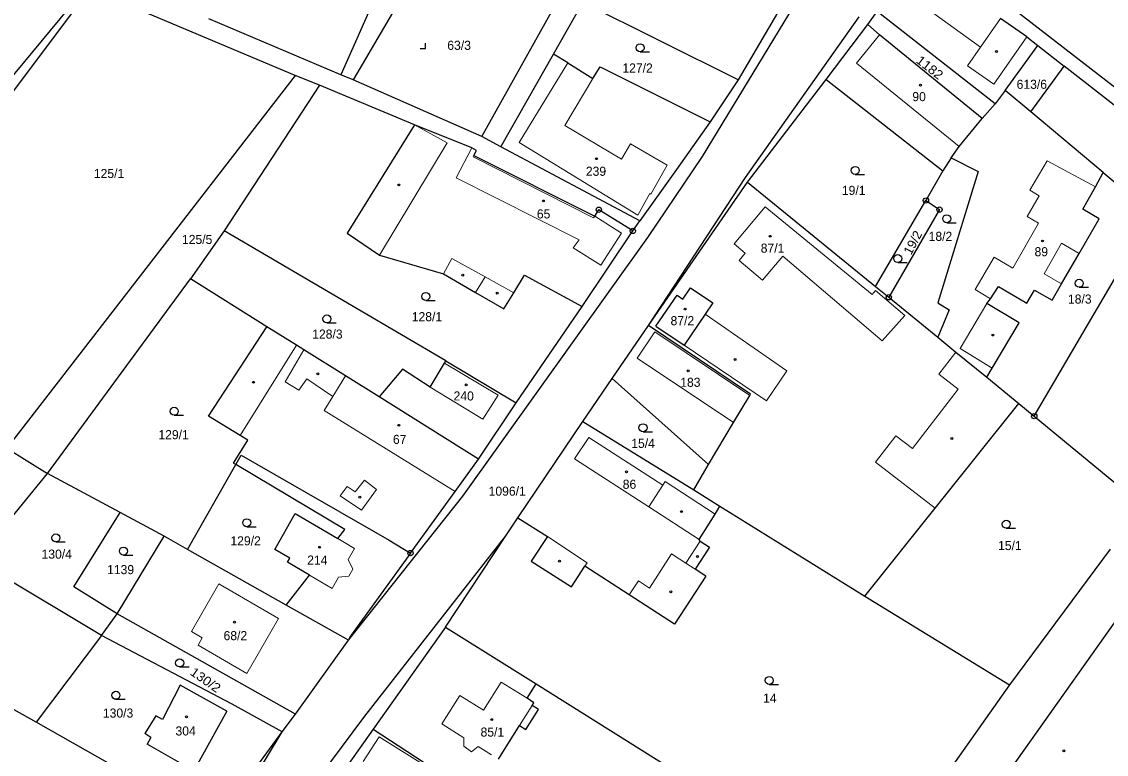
# Model space of a CAD drawing. Extents: x -694609 to -690140, y -1033292 to -1029794.
# Drawn here: x -692506.4 to -692303.2, y -1031705.3 to -1031568.1 of the extents above; entities that cross this region are included whole.
import ezdxf
from ezdxf.enums import TextEntityAlignment as Align

# ---------------------------------------------------------------- set-up
doc = ezdxf.new("R2010")
doc.units = 0
doc.header["$LTSCALE"] = 0.68
for name, color, linetype, lineweight in [('1', 7, 'Continuous', 25), ('3', 7, 'Continuous', 25), ('4', 7, 'Continuous', 13), ('5', 7, 'Continuous', 25), ('8', 7, 'Continuous', 25)]:
    doc.layers.add(name, color=color, linetype=linetype, lineweight=lineweight)
doc.layers.add('2', color=7, linetype='Continuous')

msp = doc.modelspace()

# ---------------------------------------------------------------- linework, layer by layer
at = {"layer": '1'}
for p, q in [((-692378.81, -1031593.37), (-692351.95, -1031549.08)), ((-692428.58, -1031552.29), (-692444.25, -1031578.99)), ((-692435.86, -1031553.94), (-692446.6, -1031578.05)), ((-692273.27, -1031602.4), (-692330.34, -1031558.16)), ((-692546.37, -1031624.62), (-692494.27, -1031561.65)), ((-692542.42, -1031627.11), (-692493.57, -1031562)), ((-692455.1, -1031578.2), (-692493.57, -1031562)), ((-692420.15, -1031589.65), (-692405.41, -1031563.18)), ((-692406.71, -1031574.21), (-692401.26, -1031564.53)), ((-692324.02, -1031583.53), (-692346.14, -1031566.21)), ((-692446.6, -1031578.05), (-692471.27, -1031567.56)), ((-692370.79, -1031597.28), (-692349.51, -1031567.24)), ((-692318.1, -1031570.94), (-692323.02, -1031567.51)), ((-692355.65, -1031578.92), (-692347.88, -1031568.63)), ((-692326.43, -1031586.25), (-692345.68, -1031570.59)), ((-692322.14, -1031581), (-692316.04, -1031572.55)), ((-692318.1, -1031570.94), (-692316.04, -1031572.55)), ((-692316.04, -1031572.55), (-692311.08, -1031576.44)), ((-692416.63, -1031591.56), (-692406.71, -1031574.21)), ((-692404.06, -1031575.84), (-692406.71, -1031574.21)), ((-692404.06, -1031575.84), (-692399.35, -1031578.78)), ((-692399.35, -1031578.78), (-692397.97, -1031576.56)), ((-692397.97, -1031576.56), (-692377.39, -1031586.86)), ((-692317.35, -1031585.02), (-692311.08, -1031576.44)), ((-692278.15, -1031602.2), (-692311.08, -1031576.44)), ((-692455.1, -1031578.2), (-692509.11, -1031648.01)), ((-692450.6, -1031579.99), (-692455.1, -1031578.2)), ((-692444.25, -1031578.99), (-692446.6, -1031578.05)), ((-692450.6, -1031579.99), (-692468.43, -1031607.31)), ((-692432.76, -1031587.45), (-692450.6, -1031579.99)), ((-692420.15, -1031589.65), (-692444.25, -1031578.99)), ((-692372.16, -1031579.03), (-692377.39, -1031586.86)), ((-692370.39, -1031598.15), (-692355.65, -1031578.92)), ((-692355.65, -1031578.92), (-692333.82, -1031596.07)), ((-692322.14, -1031581), (-692324.02, -1031583.53)), ((-692317.35, -1031585.02), (-692322.14, -1031581)), ((-692326.43, -1031586.25), (-692324.02, -1031583.53)), ((-692377.39, -1031586.86), (-692383.68, -1031595.82)), ((-692330.76, -1031591.49), (-692326.43, -1031586.25)), ((-692303.76, -1031596.37), (-692317.35, -1031585.02)), ((-692432.76, -1031587.45), (-692445.38, -1031607.72)), ((-692422.03, -1031591.76), (-692432.76, -1031587.45)), ((-692416.63, -1031591.56), (-692420.15, -1031589.65)), ((-692421.15, -1031592.23), (-692422.03, -1031591.76)), ((-692421.63, -1031593.17), (-692421.15, -1031592.23)), ((-692390.58, -1031605.45), (-692416.63, -1031591.56)), ((-692332.22, -1031593.61), (-692330.76, -1031591.49)), ((-692421.63, -1031593.17), (-692399.01, -1031604.57)), ((-692389.09, -1031608.56), (-692378.81, -1031593.37)), ((-692332.22, -1031593.61), (-692333.82, -1031596.07)), ((-692332.22, -1031593.61), (-692327.2, -1031596.19)), ((-692383.68, -1031595.82), (-692390.58, -1031605.45)), ((-692333.82, -1031596.07), (-692336.98, -1031601.61)), ((-692327.2, -1031596.19), (-692334.77, -1031620.8)), ((-692303.76, -1031596.37), (-692294.5, -1031604.11)), ((-692388.92, -1031625), (-692370.79, -1031597.28)), ((-692388.92, -1031625), (-692370.39, -1031598.15)), ((-692370.39, -1031598.15), (-692346.41, -1031617.72)), ((-692346.41, -1031617.72), (-692336.98, -1031601.61)), ((-692336.98, -1031601.61), (-692334.43, -1031603.32)), ((-692399.01, -1031604.57), (-692398.24, -1031603.34)), ((-692391.88, -1031607.32), (-692398.24, -1031603.34)), ((-692334.43, -1031603.32), (-692343.93, -1031619.74)), ((-692308.26, -1031611.52), (-692304.51, -1031605.04)), ((-692304.51, -1031605.04), (-692307.58, -1031603.22)), ((-692391.88, -1031607.32), (-692390.58, -1031605.45)), ((-692445.38, -1031607.72), (-692439.36, -1031611.84)), ((-692423.7, -1031656.97), (-692389.09, -1031608.56)), ((-692401.36, -1031621.44), (-692391.88, -1031607.32)), ((-692439.36, -1031611.84), (-692427.37, -1031615.38)), ((-692311.57, -1031617.22), (-692308.26, -1031611.52)), ((-692501.49, -1031652.74), (-692474.72, -1031616.29)), ((-692460.42, -1031625.25), (-692474.72, -1031616.29)), ((-692427.37, -1031615.38), (-692421.34, -1031618.84)), ((-692414.18, -1031618.89), (-692412.16, -1031615.61)), ((-692412.16, -1031615.61), (-692401.36, -1031621.44)), ((-692316.68, -1031642.01), (-692301.64, -1031616.32)), ((-692313.32, -1031620.27), (-692311.57, -1031617.22)), ((-692421.34, -1031618.84), (-692416.02, -1031621.89)), ((-692416.02, -1031621.89), (-692414.18, -1031618.89)), ((-692387.58, -1031625.14), (-692383.57, -1031619.37)), ((-692383.57, -1031619.37), (-692382.53, -1031620.1)), ((-692382.53, -1031620.1), (-692381.09, -1031617.95)), ((-692381.09, -1031617.95), (-692376.9, -1031620.81)), ((-692346.41, -1031617.72), (-692343.93, -1031619.74)), ((-692318.09, -1031620.86), (-692316.64, -1031618.4)), ((-692316.64, -1031618.4), (-692313.32, -1031620.27)), ((-692376.9, -1031620.81), (-692378.36, -1031622.93)), ((-692343.93, -1031619.74), (-692334.74, -1031627.24)), ((-692334.77, -1031620.8), (-692332.64, -1031622.09)), ((-692325.54, -1031620.92), (-692324.89, -1031620.04)), ((-692319.54, -1031624.55), (-692325.54, -1031620.92)), ((-692413.75, -1031639.49), (-692401.36, -1031621.44)), ((-692378.36, -1031622.93), (-692382.25, -1031628.74)), ((-692332.64, -1031622.09), (-692334.74, -1031627.24)), ((-692471.34, -1031642.04), (-692460.42, -1031625.25)), ((-692454.87, -1031628.73), (-692460.42, -1031625.25)), ((-692395.72, -1031634.95), (-692388.92, -1031625)), ((-692369.81, -1031637.86), (-692388.92, -1031625)), ((-692387.58, -1031625.14), (-692382.25, -1031628.74)), ((-692324.54, -1031632.99), (-692319.54, -1031624.55)), ((-692334.74, -1031627.24), (-692331.35, -1031630.01)), ((-692453.48, -1031629.6), (-692454.87, -1031628.73)), ((-692445.68, -1031634.48), (-692453.48, -1031629.6)), ((-692331.35, -1031630.01), (-692325.56, -1031634.73)), ((-692435.05, -1031633.19), (-692439.39, -1031638.41)), ((-692429.85, -1031636.57), (-692435.05, -1031633.19)), ((-692429.85, -1031636.57), (-692427.17, -1031632.06)), ((-692427.17, -1031632.06), (-692426.91, -1031631.63)), ((-692426.91, -1031631.63), (-692413.75, -1031639.49)), ((-692325.56, -1031634.73), (-692324.54, -1031632.99)), ((-692439.39, -1031638.41), (-692445.68, -1031634.48)), ((-692401.23, -1031643.01), (-692395.72, -1031634.95)), ((-692395.72, -1031634.95), (-692377.71, -1031651.07)), ((-692325.56, -1031634.73), (-692319.57, -1031639.63)), ((-692420.8, -1031650.06), (-692439.39, -1031638.41)), ((-692420.8, -1031650.06), (-692413.75, -1031639.49)), ((-692373.01, -1031643.22), (-692369.96, -1031638.12)), ((-692369.96, -1031638.12), (-692369.81, -1031637.86)), ((-692335.23, -1031659.23), (-692319.57, -1031639.63)), ((-692319.57, -1031639.63), (-692316.68, -1031642.01)), ((-692465.4, -1031645.65), (-692471.34, -1031642.04)), ((-692413.44, -1031661.04), (-692401.23, -1031643.01)), ((-692401.23, -1031643.01), (-692380.47, -1031655.82)), ((-692377.71, -1031651.07), (-692373.01, -1031643.22)), ((-692316.68, -1031642.01), (-692296.39, -1031658.75)), ((-692463.99, -1031646.5), (-692465.4, -1031645.65)), ((-692466.68, -1031650.79), (-692463.99, -1031646.5)), ((-692509.11, -1031648.01), (-692501.49, -1031652.74)), ((-692466.25, -1031651.07), (-692465.23, -1031649.29)), ((-692465.23, -1031649.29), (-692437.54, -1031665.25)), ((-692475.31, -1031666.97), (-692466.25, -1031651.07)), ((-692466.25, -1031651.07), (-692466.68, -1031650.79)), ((-692445.82, -1031663.24), (-692466.25, -1031651.07)), ((-692425.18, -1031656.1), (-692420.8, -1031650.06)), ((-692380.47, -1031655.82), (-692377.71, -1031651.07)), ((-692514.87, -1031669.07), (-692501.49, -1031652.74)), ((-692487.91, -1031660.06), (-692501.49, -1031652.74)), ((-692380.47, -1031655.82), (-692375.57, -1031658.84)), ((-692445.12, -1031683.98), (-692423.7, -1031656.97)), ((-692433.52, -1031667.65), (-692425.18, -1031656.1)), ((-692376.48, -1031660.35), (-692375.57, -1031658.84)), ((-692375.57, -1031658.84), (-692348.43, -1031675.74)), ((-692348.43, -1031675.74), (-692335.23, -1031659.23)), ((-692496.61, -1031673.98), (-692487.91, -1031660.06)), ((-692479.67, -1031664.51), (-692487.91, -1031660.06)), ((-692458.94, -1031666.99), (-692455.14, -1031660.26)), ((-692455.14, -1031660.26), (-692447.15, -1031664.95)), ((-692415.66, -1031664.41), (-692413.44, -1031661.04)), ((-692413.44, -1031661.04), (-692407.88, -1031664.57)), ((-692379.46, -1031665.13), (-692376.48, -1031660.35)), ((-692447.15, -1031664.95), (-692445.82, -1031663.24)), ((-692488.47, -1031679.06), (-692479.67, -1031664.51)), ((-692475.31, -1031666.97), (-692479.67, -1031664.51)), ((-692442.05, -1031698.19), (-692415.66, -1031664.41)), ((-692437.54, -1031665.25), (-692433.52, -1031667.65)), ((-692426.96, -1031681.51), (-692415.66, -1031664.41)), ((-692407.88, -1031664.57), (-692410.91, -1031669.2)), ((-692379.29, -1031665.4), (-692379.46, -1031665.13)), ((-692456.84, -1031677.42), (-692475.31, -1031666.97)), ((-692456.14, -1031668.62), (-692458.94, -1031666.99)), ((-692433.52, -1031667.65), (-692444.64, -1031683.05)), ((-692302.47, -1031666.94), (-692321.31, -1031692.32)), ((-692491.42, -1031683.11), (-692514.87, -1031669.07)), ((-692456.58, -1031669.39), (-692456.14, -1031668.62)), ((-692452.47, -1031671.79), (-692456.58, -1031669.39)), ((-692410.91, -1031669.2), (-692403.34, -1031673.98)), ((-692403.34, -1031673.98), (-692400.85, -1031670.09)), ((-692392.56, -1031675.45), (-692400.85, -1031670.09)), ((-692456.84, -1031677.42), (-692452.47, -1031671.79)), ((-692378.23, -1031671.97), (-692384.06, -1031681)), ((-692378.23, -1031671.97), (-692380.19, -1031670.67)), ((-692488.47, -1031679.06), (-692496.61, -1031673.98)), ((-692384.06, -1031681), (-692392.56, -1031675.45)), ((-692348.43, -1031675.74), (-692321.31, -1031692.32)), ((-692445.12, -1031683.98), (-692456.84, -1031677.42)), ((-692334.77, -1031727.41), (-692299.54, -1031677.74)), ((-692491.42, -1031683.11), (-692488.47, -1031679.06)), ((-692455.08, -1031697.82), (-692488.47, -1031679.06)), ((-692426.96, -1031681.51), (-692440.5, -1031700.65)), ((-692426.96, -1031681.51), (-692410, -1031692.14)), ((-692491.42, -1031683.11), (-692503.62, -1031699.3)), ((-692466.9, -1031695.97), (-692491.42, -1031683.11)), ((-692455.08, -1031697.82), (-692445.12, -1031683.98)), ((-692445.12, -1031683.98), (-692444.64, -1031683.05)), ((-692503.62, -1031699.3), (-692518.37, -1031691.13)), ((-692476.65, -1031692.38), (-692480, -1031698.85)), ((-692467.92, -1031697.25), (-692476.65, -1031692.38)), ((-692411.7, -1031694.86), (-692410, -1031692.14)), ((-692410, -1031692.14), (-692348.49, -1031730.69)), ((-692321.31, -1031692.32), (-692348.49, -1031730.69)), ((-692457.55, -1031701.11), (-692466.9, -1031695.97)), ((-692410.4, -1031695.68), (-692411.7, -1031694.86)), ((-692410.75, -1031696.23), (-692410.4, -1031695.68)), ((-692409.56, -1031696.97), (-692410.75, -1031696.23)), ((-692492.12, -1031765.22), (-692442.05, -1031698.19)), ((-692481.24, -1031698.17), (-692483.28, -1031701.48)), ((-692480, -1031698.85), (-692481.24, -1031698.17)), ((-692467.92, -1031697.25), (-692474.09, -1031708.43)), ((-692457.55, -1031701.11), (-692455.08, -1031697.82)), ((-692411.89, -1031700.68), (-692409.56, -1031696.97)), ((-692487.5, -1031708.49), (-692503.62, -1031699.3)), ((-692440.5, -1031700.65), (-692422.66, -1031712.29)), ((-692417.06, -1031706.27), (-692413.08, -1031699.93)), ((-692413.08, -1031699.93), (-692411.89, -1031700.68)), ((-692482.15, -1031702.21), (-692483.28, -1031701.48)), ((-692482.15, -1031702.21), (-692482.82, -1031703.44)), ((-692470.09, -1031718.27), (-692457.55, -1031701.11)), ((-692465.03, -1031713.42), (-692457.55, -1031701.11)), ((-692474.09, -1031708.43), (-692482.82, -1031703.44))]:
    msp.add_line(p, q, dxfattribs=at)
for points in [[(-692361.4, -1031560.66), (-692372.16, -1031579.03), (-692401.26, -1031564.53)], [(-692345.68, -1031570.59), (-692347.88, -1031568.63), (-692346.14, -1031566.21)], [(-692307.58, -1031603.22), (-692305.24, -1031599.08), (-692303.76, -1031596.37)], [(-692426.91, -1031631.63), (-692468.43, -1031607.31), (-692474.72, -1031616.29)], [(-692324.89, -1031620.04), (-692323.39, -1031617.72), (-692318.09, -1031620.86)], [(-692379.29, -1031665.4), (-692377.54, -1031666.56), (-692380.19, -1031670.67)], [(-692440.5, -1031700.65), (-692451.98, -1031716.89), (-692465.89, -1031734.84)]]:
    msp.add_lwpolyline(points, dxfattribs=at)
at = {"layer": '3'}
for p, q in [((-692390.523, -1031573.76), (-692388.773, -1031573.76)), ((-692350.223, -1031596.72), (-692348.473, -1031596.72)), ((-692333.083, -1031605.78), (-692331.333, -1031605.78)), ((-692342.253, -1031613.24), (-692340.503, -1031613.24)), ((-692308.273, -1031617.87), (-692306.523, -1031617.87)), ((-692430.663, -1031620.34), (-692428.913, -1031620.34)), ((-692449.193, -1031624.53), (-692447.443, -1031624.53)), ((-692477.783, -1031641.84), (-692476.033, -1031641.84)), ((-692389.973, -1031644.92), (-692388.223, -1031644.92)), ((-692464.193, -1031662.72), (-692462.443, -1031662.72)), ((-692321.933, -1031663), (-692320.183, -1031663)), ((-692499.953, -1031665.56), (-692498.203, -1031665.56)), ((-692487.293, -1031668.03), (-692485.543, -1031668.03)), ((-692476.763, -1031688.98), (-692475.013, -1031688.98)), ((-692366.323, -1031692.27), (-692364.573, -1031692.27)), ((-692488.693, -1031695.05), (-692486.943, -1031695.05))]:
    msp.add_line(p, q, dxfattribs=at)
msp.add_lwpolyline([(-692431.691, -1031573.14), (-692430.69, -1031573.14), (-692430.69, -1031572.14)], dxfattribs=at)
for centre in [(-692390.5229, -1031573.0098), (-692350.2229, -1031595.9698), (-692333.0829, -1031605.0298), (-692342.2529, -1031612.4898), (-692308.2729, -1031617.1198), (-692430.6629, -1031619.5898), (-692449.1929, -1031623.7798), (-692477.7829, -1031641.0898), (-692389.9729, -1031644.1698), (-692464.1929, -1031661.9698), (-692321.9329, -1031662.2498), (-692499.9529, -1031664.8098), (-692487.2929, -1031667.2798), (-692476.7629, -1031688.2298), (-692366.3229, -1031691.5198), (-692488.6929, -1031694.2998)]:
    msp.add_circle(centre, 0.75, dxfattribs=at)
at = {"layer": '4'}
for p, q in [((-692336.63, -1031565.78), (-692326.78, -1031572.9)), ((-692326.78, -1031572.9), (-692323.02, -1031567.51)), ((-692345.68, -1031570.59), (-692349.97, -1031575.86)), ((-692324.28, -1031579.8), (-692318.1, -1031570.94)), ((-692329.2, -1031576.37), (-692326.78, -1031572.9)), ((-692404.06, -1031575.84), (-692413.18, -1031590.73)), ((-692330.76, -1031591.49), (-692349.97, -1031575.86)), ((-692329.2, -1031576.37), (-692324.28, -1031579.8)), ((-692404.61, -1031587.55), (-692399.35, -1031578.78)), ((-692432.76, -1031587.45), (-692426.63, -1031590.83)), ((-692393.99, -1031593.87), (-692404.61, -1031587.55)), ((-692426.63, -1031590.83), (-692439.36, -1031611.84)), ((-692390.93, -1031604.37), (-692413.18, -1031590.73)), ((-692424.98, -1031597.37), (-692422.03, -1031591.76)), ((-692392.32, -1031591.01), (-692393.99, -1031593.87)), ((-692385.42, -1031595.02), (-692392.32, -1031591.01)), ((-692421.63, -1031593.17), (-692421.76, -1031593.45)), ((-692421.76, -1031593.45), (-692399.22, -1031604.85)), ((-692388.51, -1031600.42), (-692385.42, -1031595.02)), ((-692314.29, -1031594.21), (-692317.5, -1031599.69)), ((-692305.24, -1031599.08), (-692314.29, -1031594.21)), ((-692401.93, -1031608.95), (-692424.98, -1031597.37)), ((-692390.93, -1031604.37), (-692388.69, -1031600.32)), ((-692388.69, -1031600.32), (-692388.51, -1031600.42)), ((-692315.76, -1031600.74), (-692318.02, -1031604.62)), ((-692317.5, -1031599.69), (-692315.76, -1031600.74)), ((-692367.11, -1031602.8), (-692372.92, -1031609.76)), ((-692367.11, -1031602.8), (-692347.05, -1031619.21)), ((-692399.22, -1031604.85), (-692399.01, -1031604.57)), ((-692399.01, -1031604.57), (-692394.02, -1031607.75)), ((-692318.02, -1031604.62), (-692315.9, -1031605.89)), ((-692315.9, -1031605.89), (-692320.69, -1031614.28)), ((-692403.03, -1031610.51), (-692401.93, -1031608.95)), ((-692397.9, -1031613.74), (-692394.02, -1031607.75)), ((-692397.9, -1031613.74), (-692403.03, -1031610.51)), ((-692370.83, -1031611.5), (-692372.92, -1031609.76)), ((-692311.56, -1031609.62), (-692314.85, -1031615.33)), ((-692308.26, -1031611.52), (-692311.56, -1031609.62)), ((-692427.37, -1031615.38), (-692425.76, -1031612.45)), ((-692425.76, -1031612.45), (-692419.55, -1031615.9)), ((-692370.83, -1031611.5), (-692371.97, -1031612.87)), ((-692371.97, -1031612.87), (-692367.56, -1031616.54)), ((-692367.56, -1031616.54), (-692363.79, -1031612.02)), ((-692345.2, -1031627.91), (-692363.79, -1031612.02)), ((-692324.22, -1031612.25), (-692327.74, -1031618.28)), ((-692320.69, -1031614.28), (-692324.22, -1031612.25)), ((-692314.85, -1031615.33), (-692311.57, -1031617.22)), ((-692421.34, -1031618.84), (-692419.55, -1031615.9)), ((-692419.55, -1031615.9), (-692414.18, -1031618.89)), ((-692347.05, -1031619.21), (-692346.41, -1031618.49)), ((-692346.41, -1031618.49), (-692340.91, -1031623.15)), ((-692327.74, -1031618.28), (-692324.89, -1031620.04)), ((-692325.54, -1031620.92), (-692330.55, -1031629.36)), ((-692363.01, -1031633.5), (-692378.36, -1031622.93)), ((-692340.91, -1031623.15), (-692345.2, -1031627.91)), ((-692391.04, -1031631.12), (-692387.73, -1031626.19)), ((-692369.96, -1031638.12), (-692387.73, -1031626.19)), ((-692465.4, -1031645.65), (-692454.87, -1031628.73)), ((-692382.25, -1031628.74), (-692366.84, -1031639.16)), ((-692330.55, -1031629.36), (-692324.54, -1031632.99)), ((-692453.48, -1031629.6), (-692457.01, -1031635.56)), ((-692373.01, -1031643.22), (-692391.04, -1031631.12)), ((-692331.35, -1031630.01), (-692334.54, -1031634.17)), ((-692363.01, -1031633.5), (-692366.84, -1031639.16)), ((-692457.01, -1031635.56), (-692454.41, -1031637.12)), ((-692454.41, -1031637.12), (-692452.96, -1031635.04)), ((-692452.96, -1031635.04), (-692448.06, -1031638.33)), ((-692448.06, -1031638.33), (-692445.68, -1031634.48)), ((-692334.54, -1031634.17), (-692330.94, -1031636.93)), ((-692419.96, -1031642.57), (-692429.85, -1031636.57)), ((-692330.94, -1031636.93), (-692339.5, -1031648.09)), ((-692449.68, -1031640.97), (-692448.06, -1031638.33)), ((-692425.18, -1031656.1), (-692449.68, -1031640.97)), ((-692342.64, -1031645.69), (-692346.44, -1031650.64)), ((-692339.5, -1031648.09), (-692342.64, -1031645.69)), ((-692400.11, -1031645.99), (-692402.81, -1031650.01)), ((-692400.11, -1031645.99), (-692386.24, -1031654.93)), ((-692402.81, -1031650.01), (-692388.89, -1031659.02)), ((-692335.23, -1031659.23), (-692346.44, -1031650.64)), ((-692446.71, -1031656.92), (-692445.36, -1031655.16)), ((-692443.92, -1031656.18), (-692445.36, -1031655.16)), ((-692442.12, -1031654.02), (-692443.92, -1031656.18)), ((-692442.71, -1031659.64), (-692439.9, -1031655.77)), ((-692439.9, -1031655.77), (-692442.12, -1031654.02)), ((-692386.24, -1031654.93), (-692388.89, -1031659.02)), ((-692386.24, -1031654.93), (-692385.82, -1031654.28)), ((-692385.82, -1031654.28), (-692376.48, -1031660.35)), ((-692446.71, -1031656.92), (-692442.71, -1031659.64)), ((-692388.89, -1031659.02), (-692379.46, -1031665.13)), ((-692447.15, -1031664.95), (-692444, -1031666.79)), ((-692407.88, -1031664.57), (-692400.45, -1031669.47)), ((-692379.29, -1031665.4), (-692381.96, -1031669.54)), ((-692444, -1031666.79), (-692445.18, -1031668.88)), ((-692384.66, -1031667.82), (-692388.78, -1031674.2)), ((-692381.96, -1031669.54), (-692384.66, -1031667.82)), ((-692445.18, -1031668.88), (-692444.34, -1031670.67)), ((-692400.85, -1031670.09), (-692400.45, -1031669.47)), ((-692380.19, -1031670.67), (-692381.96, -1031669.54)), ((-692448.21, -1031674.28), (-692452.47, -1031671.79)), ((-692447.03, -1031672.19), (-692448.21, -1031674.28)), ((-692445.08, -1031671.97), (-692447.03, -1031672.19)), ((-692444.34, -1031670.67), (-692445.08, -1031671.97)), ((-692469.42, -1031673.44), (-692474.56, -1031682.32)), ((-692458.22, -1031679.92), (-692469.42, -1031673.44)), ((-692390.79, -1031672.84), (-692392.56, -1031675.45)), ((-692388.78, -1031674.2), (-692390.79, -1031672.84)), ((-692474.56, -1031682.32), (-692472.52, -1031683.51)), ((-692473.32, -1031684.92), (-692472.52, -1031683.51)), ((-692411.7, -1031694.86), (-692416.51, -1031691.83)), ((-692427.63, -1031699.66), (-692424.27, -1031694.32)), ((-692413.08, -1031699.93), (-692410.75, -1031696.23)), ((-692423.52, -1031702.25), (-692427.63, -1031699.66)), ((-692442.42, -1031706.71), (-692439.38, -1031702.08)), ((-692420.54, -1031713.84), (-692439.38, -1031702.08)), ((-692420.87, -1031703.88), (-692422.07, -1031704.86)), ((-692420.87, -1031703.88), (-692418.37, -1031705.46))]:
    msp.add_line(p, q, dxfattribs=at)
for points in [[(-692419.96, -1031642.57), (-692417.13, -1031638.06), (-692427.17, -1031632.06)], [(-692458.22, -1031679.92), (-692464.16, -1031690.22), (-692473.32, -1031684.92)], [(-692416.51, -1031691.83), (-692419.83, -1031697.11), (-692424.27, -1031694.32)], [(-692423.52, -1031702.25), (-692423.53, -1031703.8), (-692422.07, -1031704.86)]]:
    msp.add_lwpolyline(points, dxfattribs=at)
at = {"layer": '5'}
for centre in [(-692323.7468, -1031573.7192), (-692337.9868, -1031580.0092), (-692398.6668, -1031593.7892), (-692435.6968, -1031598.6992), (-692408.6368, -1031601.6992), (-692366.1568, -1031608.3192), (-692315.1368, -1031609.1992), (-692423.7468, -1031615.5992), (-692417.2668, -1031618.9692), (-692382.0968, -1031621.9392), (-692324.4368, -1031626.8192), (-692372.7368, -1031631.3792), (-692381.5068, -1031633.5092), (-692462.9268, -1031635.6692), (-692450.8868, -1031634.0992), (-692423.0768, -1031636.1292), (-692435.7268, -1031643.7192), (-692332.1368, -1031646.2092), (-692393.0668, -1031652.4292), (-692442.9968, -1031657.1792), (-692382.7568, -1031659.8892), (-692450.5468, -1031666.5692), (-692379.7868, -1031668.2992), (-692405.6168, -1031669.1892), (-692384.7768, -1031674.9092), (-692466.5068, -1031680.5992), (-692475.4868, -1031698.3392), (-692418.3168, -1031698.8592), (-692311.1168, -1031704.6892)]:
    msp.add_circle(centre, 0.175, dxfattribs=at)
at = {"layer": '8'}
for centre, radius in [((-692336.98, -1031601.6099), 0.5), ((-692398.24, -1031603.3399), 0.5), ((-692336.98, -1031601.6099), 0.0303), ((-692334.43, -1031603.3199), 0.5), ((-692398.24, -1031603.3399), 0.0303), ((-692334.43, -1031603.3199), 0.0303), ((-692391.88, -1031607.3199), 0.5), ((-692391.88, -1031607.3199), 0.0303), ((-692343.93, -1031619.7399), 0.5), ((-692343.93, -1031619.7399), 0.0303), ((-692316.68, -1031642.0099), 0.5), ((-692316.68, -1031642.0099), 0.0303), ((-692433.52, -1031667.6499), 0.5), ((-692433.52, -1031667.6499), 0.0303)]:
    msp.add_circle(centre, radius, dxfattribs=at)

# ---------------------------------------------------------------- texts
at = {"layer": '2'}
for s, p in [('63/3', (-692424.419, -1031573.395)), ('127/2', (-692390.99, -1031577.645)), ('613/6', (-692317.14, -1031580.695)), ('90', (-692338.259, -1031583.005)), ('125/1', (-692489.99, -1031597.405)), ('239', (-692398.779, -1031596.985)), ('19/1', (-692350.509, -1031600.565)), ('65', (-692408.589, -1031604.975)), ('125/5', (-692473.49, -1031609.755)), ('18/2', (-692334.259, -1031609.175)), ('87/1', (-692365.709, -1031611.385)), ('89', (-692315.369, -1031612.055)), ('18/3', (-692308.159, -1031620.922)), ('128/1', (-692430.44, -1031624.225)), ('87/2', (-692382.599, -1031624.975)), ('128/3', (-692449.09, -1031627.485)), ('183', (-692381.099, -1031636.515)), ('240', (-692423.559, -1031639.075)), ('129/1', (-692477.9, -1031646.325)), ('67', (-692435.549, -1031647.215)), ('15/4', (-692389.959, -1031647.955)), ('86', (-692392.509, -1031655.615)), ('1096/1', (-692415.41, -1031656.905)), ('129/2', (-692464.41, -1031666.215)), ('15/1', (-692321.249, -1031667.095)), ('130/4', (-692499.79, -1031668.705)), ('214', (-692450.979, -1031669.815)), ('1139', (-692487.83, -1031671.605)), ('68/2', (-692466.329, -1031683.975)), ('14', (-692366.219, -1031695.685)), ('130/3', (-692488.3, -1031698.475)), ('304', (-692475.649, -1031701.825)), ('85/1', (-692418.189, -1031702.035))]:
    msp.add_text(s, height=1.7, dxfattribs=at).set_placement(p, align=Align.CENTER)
for s, rotation, width, p in [('1182', 322, 1.1, (-692336.7833, -1031577.368)), ('19/2', 62, 1.05, (-692338.6763, -1031609.8961)), ('130/2', 325, 1.1, (-692472.4045, -1031692.1116))]:
    msp.add_text(s, height=1.7, rotation=rotation, dxfattribs=dict(at, width=width)).set_placement(p, align=Align.CENTER)

doc.saveas('drawing.dxf')
